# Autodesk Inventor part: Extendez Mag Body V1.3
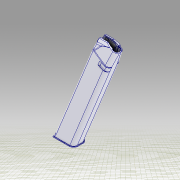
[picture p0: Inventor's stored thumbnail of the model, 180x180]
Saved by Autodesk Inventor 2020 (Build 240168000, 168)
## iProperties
Created: 2019-09
Part Number: Extendez Mag Body V1.3
Material: Steel
Document SubType Name: Modeling
Designer: johne
Density: 7.85 g/cm^3
Appearance: Default
Author: johne
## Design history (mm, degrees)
feature "Body1"
body "Solid1"
